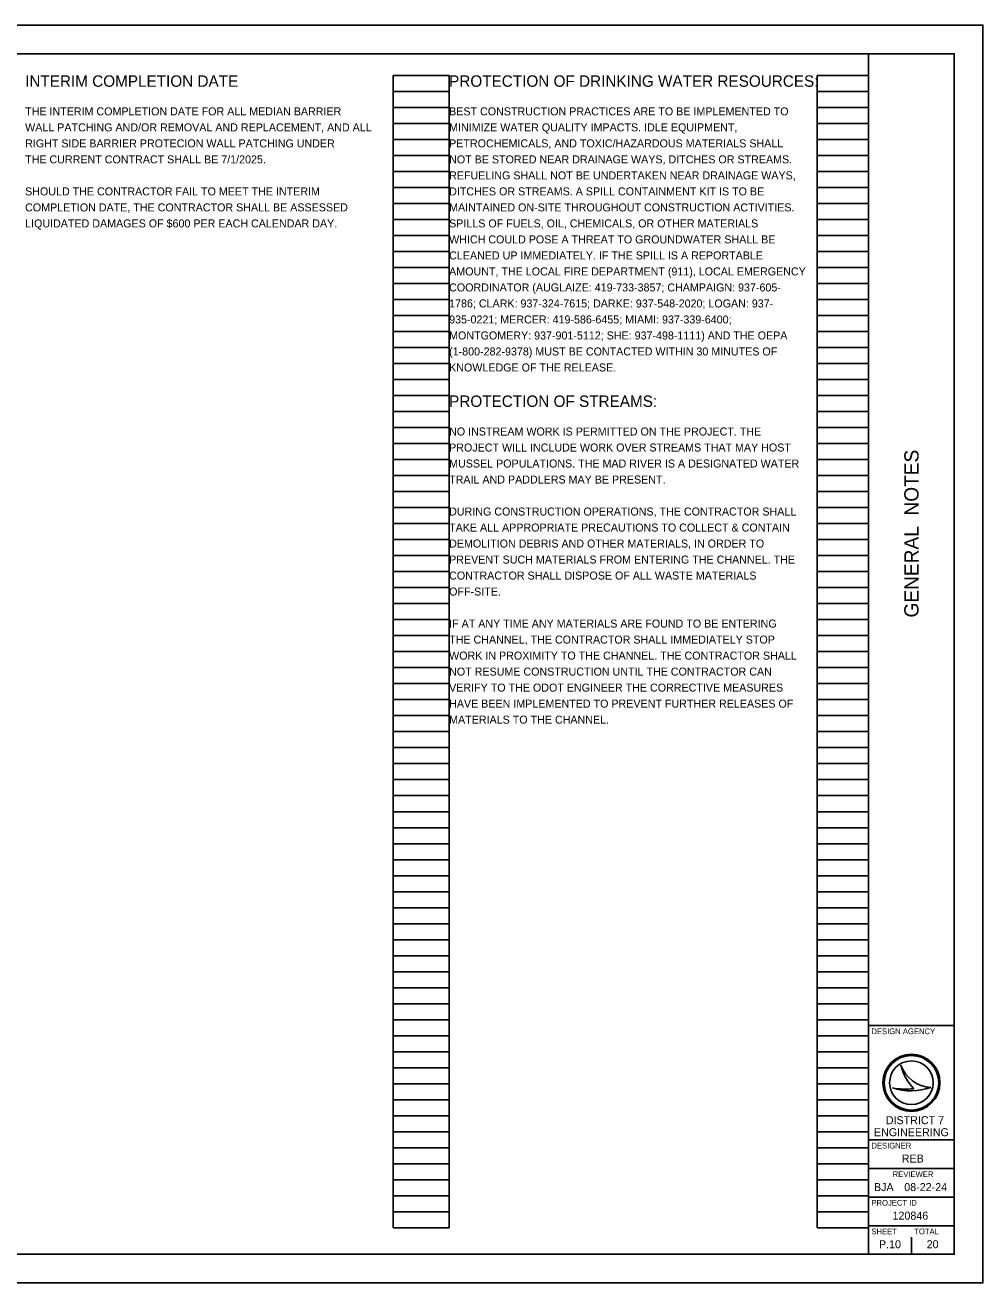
# Model space of a CAD drawing. Extents: x -18.2 to 34, y 0 to 22.
# Drawn here: x 17.24 to 34, y 0 to 22 of the extents above; entities that cross this region are included whole.
import ezdxf

# ---------------------------------------------------------------- set-up
doc = ezdxf.new("R2010")
doc.units = 0
for name, color, linetype in [('Default', 7, 'Continuous'), ('SH_Border', 7, 'Continuous'), ('SH_Cut_Line', 7, 'Continuous'), ('SH_Data', 7, 'Continuous'), ('SH_Text', 7, 'Continuous')]:
    doc.layers.add(name, color=color, linetype=linetype)

msp = doc.modelspace()

# ---------------------------------------------------------------- linework, layer by layer
at = {"layer": 'SH_Border'}
for p, q in [((32, 0.5), (32, 21.5)), ((32, 4.5), (33.5, 4.5)), ((32, 2.5), (33.5, 2.5)), ((32, 2), (33.5, 2)), ((32, 1.5), (33.5, 1.5)), ((32, 1), (33.5, 1))]:
    msp.add_line(p, q, dxfattribs=at)
msp.add_lwpolyline([(1.5, 21.5), (33.5, 21.5), (33.5, 0.5), (1.5, 0.5)], close=True, dxfattribs=at)
at = {"layer": 'SH_Cut_Line'}
msp.add_lwpolyline([(0, 0), (34, 0), (34, 22), (0, 22)], close=True, dxfattribs=at)
at = {"layer": 'SH_Data'}
for p, q in [((23.68, 0.962), (23.68, 21.122)), ((23.68, 21.122), (24.66, 21.122)), ((24.66, 0.962), (24.66, 21.122)), ((31.1, 0.962), (31.1, 21.122)), ((31.1, 21.122), (32, 21.122)), ((32, 0.962), (32, 21.122)), ((23.68, 20.842), (24.66, 20.842)), ((31.1, 20.842), (32, 20.842)), ((23.68, 20.562), (24.66, 20.562)), ((31.1, 20.562), (32, 20.562)), ((23.68, 20.282), (24.66, 20.282)), ((31.1, 20.282), (32, 20.282)), ((23.68, 20.002), (24.66, 20.002)), ((31.1, 20.002), (32, 20.002)), ((23.68, 19.722), (24.66, 19.722)), ((31.1, 19.722), (32, 19.722)), ((23.68, 19.442), (24.66, 19.442)), ((31.1, 19.442), (32, 19.442)), ((23.68, 19.162), (24.66, 19.162)), ((31.1, 19.162), (32, 19.162)), ((23.68, 18.882), (24.66, 18.882)), ((31.1, 18.882), (32, 18.882)), ((23.68, 18.602), (24.66, 18.602)), ((31.1, 18.602), (32, 18.602)), ((23.68, 18.322), (24.66, 18.322)), ((31.1, 18.322), (32, 18.322)), ((23.68, 18.042), (24.66, 18.042)), ((31.1, 18.042), (32, 18.042)), ((23.68, 17.762), (24.66, 17.762)), ((31.1, 17.762), (32, 17.762)), ((23.68, 17.482), (24.66, 17.482)), ((31.1, 17.482), (32, 17.482)), ((23.68, 17.202), (24.66, 17.202)), ((31.1, 17.202), (32, 17.202)), ((23.68, 16.922), (24.66, 16.922)), ((31.1, 16.922), (32, 16.922)), ((23.68, 16.642), (24.66, 16.642)), ((31.1, 16.642), (32, 16.642)), ((23.68, 16.362), (24.66, 16.362)), ((31.1, 16.362), (32, 16.362)), ((23.68, 16.082), (24.66, 16.082)), ((31.1, 16.082), (32, 16.082)), ((23.68, 15.802), (24.66, 15.802)), ((31.1, 15.802), (32, 15.802)), ((23.68, 15.522), (24.66, 15.522)), ((31.1, 15.522), (32, 15.522)), ((23.68, 15.242), (24.66, 15.242)), ((31.1, 15.242), (32, 15.242)), ((23.68, 14.962), (24.66, 14.962)), ((31.1, 14.962), (32, 14.962)), ((23.68, 14.682), (24.66, 14.682)), ((31.1, 14.682), (32, 14.682)), ((23.68, 14.402), (24.66, 14.402)), ((31.1, 14.402), (32, 14.402)), ((23.68, 14.122), (24.66, 14.122)), ((31.1, 14.122), (32, 14.122)), ((23.68, 13.842), (24.66, 13.842)), ((31.1, 13.842), (32, 13.842)), ((23.68, 13.562), (24.66, 13.562)), ((31.1, 13.562), (32, 13.562)), ((23.68, 13.282), (24.66, 13.282)), ((31.1, 13.282), (32, 13.282)), ((23.68, 13.002), (24.66, 13.002)), ((31.1, 13.002), (32, 13.002)), ((23.68, 12.722), (24.66, 12.722)), ((31.1, 12.722), (32, 12.722)), ((23.68, 12.442), (24.66, 12.442)), ((31.1, 12.442), (32, 12.442)), ((23.68, 12.162), (24.66, 12.162)), ((31.1, 12.162), (32, 12.162)), ((23.68, 11.882), (24.66, 11.882)), ((31.1, 11.882), (32, 11.882)), ((23.68, 11.602), (24.66, 11.602)), ((31.1, 11.602), (32, 11.602)), ((23.68, 11.322), (24.66, 11.322)), ((31.1, 11.322), (32, 11.322)), ((23.68, 11.042), (24.66, 11.042)), ((31.1, 11.042), (32, 11.042)), ((23.68, 10.762), (24.66, 10.762)), ((31.1, 10.762), (32, 10.762)), ((23.68, 10.482), (24.66, 10.482)), ((31.1, 10.482), (32, 10.482)), ((23.68, 10.202), (24.66, 10.202)), ((31.1, 10.202), (32, 10.202)), ((23.68, 9.922), (24.66, 9.922)), ((31.1, 9.922), (32, 9.922)), ((23.68, 9.642), (24.66, 9.642)), ((31.1, 9.642), (32, 9.642)), ((23.68, 9.362), (24.66, 9.362)), ((31.1, 9.362), (32, 9.362)), ((23.68, 9.082), (24.66, 9.082)), ((31.1, 9.082), (32, 9.082)), ((23.68, 8.802), (24.66, 8.802)), ((31.1, 8.802), (32, 8.802)), ((23.68, 8.522), (24.66, 8.522)), ((31.1, 8.522), (32, 8.522)), ((23.68, 8.242), (24.66, 8.242)), ((31.1, 8.242), (32, 8.242)), ((23.68, 7.962), (24.66, 7.962)), ((31.1, 7.962), (32, 7.962)), ((23.68, 7.682), (24.66, 7.682)), ((31.1, 7.682), (32, 7.682)), ((23.68, 7.402), (24.66, 7.402)), ((31.1, 7.402), (32, 7.402)), ((23.68, 7.122), (24.66, 7.122)), ((31.1, 7.122), (32, 7.122)), ((23.68, 6.842), (24.66, 6.842)), ((31.1, 6.842), (32, 6.842)), ((23.68, 6.562), (24.66, 6.562)), ((31.1, 6.562), (32, 6.562)), ((23.68, 6.282), (24.66, 6.282)), ((31.1, 6.282), (32, 6.282)), ((23.68, 6.002), (24.66, 6.002)), ((31.1, 6.002), (32, 6.002)), ((23.68, 5.722), (24.66, 5.722)), ((31.1, 5.722), (32, 5.722)), ((23.68, 5.442), (24.66, 5.442)), ((31.1, 5.442), (32, 5.442)), ((23.68, 5.162), (24.66, 5.162)), ((31.1, 5.162), (32, 5.162)), ((23.68, 4.882), (24.66, 4.882)), ((31.1, 4.882), (32, 4.882)), ((23.68, 4.602), (24.66, 4.602)), ((31.1, 4.602), (32, 4.602)), ((23.68, 4.322), (24.66, 4.322)), ((31.1, 4.322), (32, 4.322)), ((23.68, 4.042), (24.66, 4.042)), ((31.1, 4.042), (32, 4.042)), ((23.68, 3.762), (24.66, 3.762)), ((31.1, 3.762), (32, 3.762)), ((32.567, 3.81), (32.567, 3.81)), ((23.68, 3.482), (24.66, 3.482)), ((31.1, 3.482), (32, 3.482)), ((32.417, 3.41), (32.417, 3.41)), ((32.75, 3.5), (32.75, 3.5)), ((33.087, 3.419), (33.087, 3.419)), ((23.68, 3.202), (24.66, 3.202)), ((31.1, 3.202), (32, 3.202)), ((23.68, 2.922), (24.66, 2.922)), ((31.1, 2.922), (32, 2.922)), ((23.68, 2.642), (24.66, 2.642)), ((31.1, 2.642), (32, 2.642)), ((23.68, 2.362), (24.66, 2.362)), ((31.1, 2.362), (32, 2.362)), ((23.68, 2.082), (24.66, 2.082)), ((31.1, 2.082), (32, 2.082)), ((23.68, 1.802), (24.66, 1.802)), ((31.1, 1.802), (32, 1.802)), ((23.68, 1.522), (24.66, 1.522)), ((31.1, 1.522), (32, 1.522)), ((23.68, 1.242), (24.66, 1.242)), ((31.1, 1.242), (32, 1.242)), ((23.68, 0.962), (24.66, 0.962)), ((31.1, 0.962), (32, 0.962)), ((32.375, 0.675), (32.375, 0.675)), ((32.75, 0.5), (32.75, 0.8))]:
    msp.add_line(p, q, dxfattribs=at)
for radius in [0.5, 0.477, 0.477, 0.382]:
    msp.add_circle((32.75, 3.5), radius, dxfattribs=at)
for centre, radius, start, end in [((33.116, 3.998), 0.58, 198.9257, 198.9319), ((33.347, 3.97), 0.796, 191.6379, 191.6421), ((33.116, 3.998), 0.58, 198.9319, 267.1657), ((33.347, 3.97), 0.796, 191.6421, 226.0947), ((32.739, 4.37), 1.013, 251.4576, 290.0832), ((32.648, 4.654), 1.266, 259.4964, 259.4995), ((32.739, 4.37), 1.013, 251.4527, 251.4576), ((32.648, 4.654), 1.266, 259.4995, 276.6672)]:
    msp.add_arc(centre, radius, start, end, dxfattribs=at)

# ---------------------------------------------------------------- texts
at = {"layer": 'Default'}
for s, p in [('INTERIM COMPLETION DATE', (17.24, 20.922)), ('PROTECTION OF DRINKING WATER RESOURCES:', (24.66, 20.922)), ('PROTECTION OF STREAMS:', (24.66, 15.322))]:
    msp.add_text(s, height=0.2, dxfattribs=at).set_placement(p)
at = {"layer": 'SH_Data'}
msp.add_text('GENERAL  NOTES', height=0.25, rotation=90, dxfattribs=at).set_placement((32.875, 11.638))
for s, height, p in [('DESIGN AGENCY', 0.1, (32.05, 4.35)), ('DESIGNER', 0.1, (32.05, 2.35)), ('REB', 0.14, (32.581, 2.105)), ('REVIEWER', 0.1, (32.422, 1.85)), ('BJA', 0.14, (32.095, 1.605)), ('08-22-24', 0.14, (32.625, 1.605)), ('PROJECT ID', 0.1, (32.05, 1.35)), ('120846', 0.14, (32.419, 1.105)), ('SHEET', 0.1, (32.05, 0.85)), ('TOTAL', 0.1, (32.8, 0.85)), ('P.10', 0.14, (32.182, 0.605)), ('20', 0.14, (33.017, 0.605))]:
    msp.add_text(s, height=height, dxfattribs=at).set_placement(p)
at = {"layer": 'SH_Text'}
for s, p in [('THE INTERIM COMPLETION DATE FOR ALL MEDIAN BARRIER', (17.24, 20.422)), ('BEST CONSTRUCTION PRACTICES ARE TO BE IMPLEMENTED TO', (24.66, 20.422)), ('WALL PATCHING AND/OR REMOVAL AND REPLACEMENT, AND ALL', (17.24, 20.142)), ('MINIMIZE WATER QUALITY IMPACTS. IDLE EQUIPMENT, ', (24.66, 20.142)), ('RIGHT SIDE BARRIER PROTECION WALL PATCHING UNDER ', (17.24, 19.862)), ('PETROCHEMICALS, AND TOXIC/HAZARDOUS MATERIALS SHALL', (24.66, 19.862)), ('THE CURRENT CONTRACT SHALL BE 7/1/2025.    ', (17.24, 19.582)), ('NOT BE STORED NEAR DRAINAGE WAYS, DITCHES OR STREAMS.', (24.66, 19.582)), ('REFUELING SHALL NOT BE UNDERTAKEN NEAR DRAINAGE WAYS,', (24.66, 19.302)), ('SHOULD THE CONTRACTOR FAIL TO MEET THE INTERIM ', (17.24, 19.022)), ('DITCHES OR STREAMS. A SPILL CONTAINMENT KIT IS TO BE', (24.66, 19.022)), ('COMPLETION DATE, THE CONTRACTOR SHALL BE ASSESSED ', (17.24, 18.742)), ('MAINTAINED ON-SITE THROUGHOUT CONSTRUCTION ACTIVITIES.', (24.66, 18.742)), ('LIQUIDATED DAMAGES OF $600 PER EACH CALENDAR DAY.', (17.24, 18.462)), ('SPILLS OF FUELS, OIL, CHEMICALS, OR OTHER MATERIALS ', (24.66, 18.462)), ('WHICH COULD POSE A THREAT TO GROUNDWATER SHALL BE ', (24.66, 18.182)), ('CLEANED UP IMMEDIATELY. IF THE SPILL IS A REPORTABLE ', (24.66, 17.902)), ('AMOUNT, THE LOCAL FIRE DEPARTMENT (911), LOCAL EMERGENCY ', (24.66, 17.622)), ('COORDINATOR (AUGLAIZE: 419-733-3857; CHAMPAIGN: 937-605-', (24.66, 17.342)), ('1786; CLARK: 937-324-7615; DARKE: 937-548-2020; LOGAN: 937-', (24.66, 17.062)), ('935-0221; MERCER: 419-586-6455; MIAMI: 937-339-6400; ', (24.66, 16.782)), ('MONTGOMERY: 937-901-5112; SHE: 937-498-1111) AND THE OEPA ', (24.66, 16.502)), ('(1-800-282-9378) MUST BE CONTACTED WITHIN 30 MINUTES OF ', (24.66, 16.222)), ('KNOWLEDGE OF THE RELEASE.', (24.66, 15.942)), ('NO INSTREAM WORK IS PERMITTED ON THE PROJECT. THE ', (24.66, 14.822)), ('PROJECT WILL INCLUDE WORK OVER STREAMS THAT MAY HOST ', (24.66, 14.542)), ('MUSSEL POPULATIONS. THE MAD RIVER IS A DESIGNATED WATER ', (24.66, 14.262)), ('TRAIL AND PADDLERS MAY BE PRESENT. ', (24.66, 13.982)), ('DURING CONSTRUCTION OPERATIONS, THE CONTRACTOR SHALL ', (24.66, 13.422)), ('TAKE ALL APPROPRIATE PRECAUTIONS TO COLLECT & CONTAIN ', (24.66, 13.142)), ('DEMOLITION DEBRIS AND OTHER MATERIALS, IN ORDER TO ', (24.66, 12.862)), ('PREVENT SUCH MATERIALS FROM ENTERING THE CHANNEL. THE ', (24.66, 12.582)), ('CONTRACTOR SHALL DISPOSE OF ALL WASTE MATERIALS ', (24.66, 12.302)), ('OFF-SITE.', (24.66, 12.022)), ('IF AT ANY TIME ANY MATERIALS ARE FOUND TO BE ENTERING', (24.66, 11.462)), ('THE CHANNEL, THE CONTRACTOR SHALL IMMEDIATELY STOP', (24.66, 11.182)), ('WORK IN PROXIMITY TO THE CHANNEL. THE CONTRACTOR SHALL', (24.66, 10.902)), ('NOT RESUME CONSTRUCTION UNTIL THE CONTRACTOR CAN', (24.66, 10.622)), ('VERIFY TO THE ODOT ENGINEER THE CORRECTIVE MEASURES ', (24.66, 10.342)), ('HAVE BEEN IMPLEMENTED TO PREVENT FURTHER RELEASES OF ', (24.66, 10.062)), ('MATERIALS TO THE CHANNEL.', (24.66, 9.782)), ('    DISTRICT 7 ', (32.094, 2.775)), ('ENGINEERING', (32.094, 2.565))]:
    msp.add_text(s, height=0.14, dxfattribs=at).set_placement(p)

doc.saveas('drawing.dxf')
